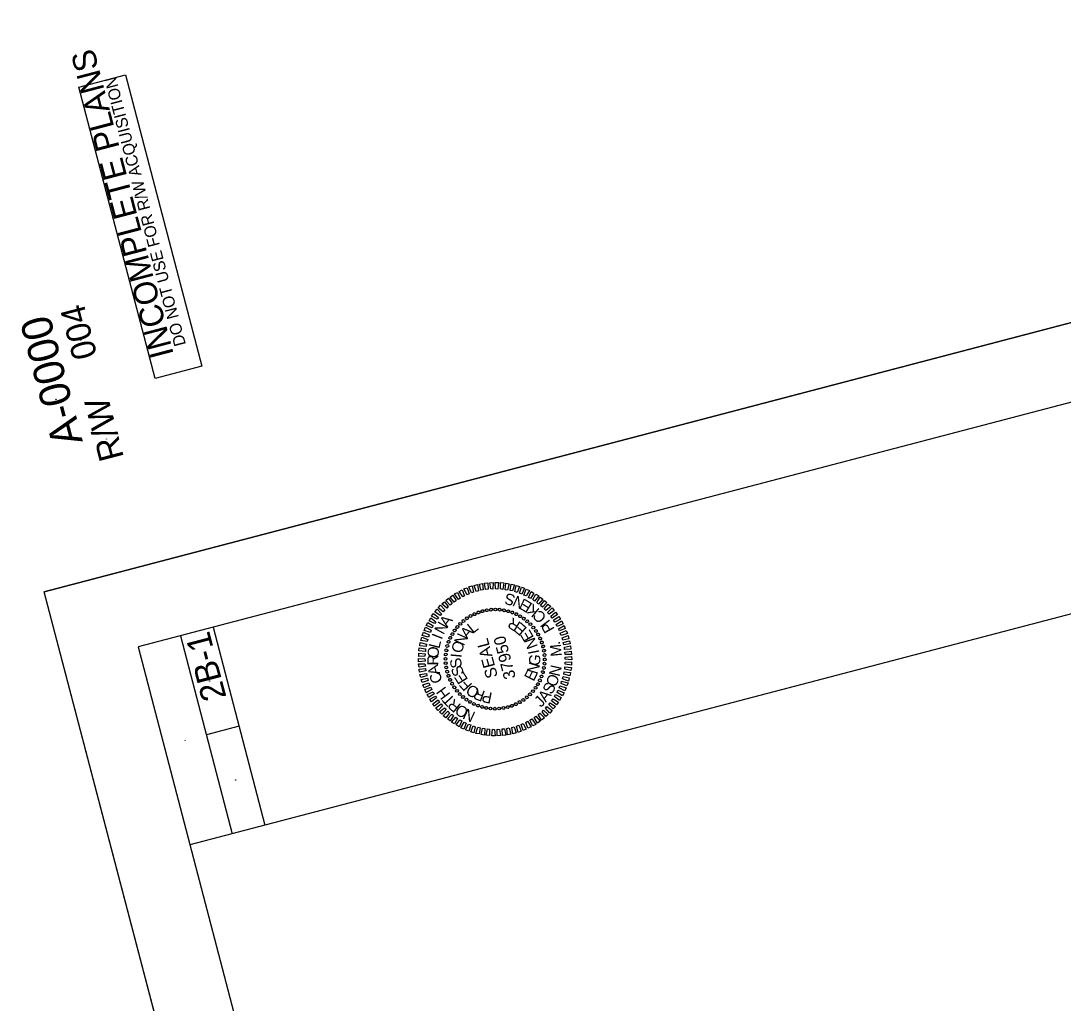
# Model space of a CAD drawing. Extents: x 1366699 to 1368206, y 878140 to 880064.
# Drawn here: x 1366699 to 1367209, y 879584 to 880064 of the extents above; entities that cross this region are included whole.
import ezdxf

# ---------------------------------------------------------------- set-up
doc = ezdxf.new("R2010")
doc.units = 0
for name, color, linetype in [('Prop Pavement Schedule Description CELL', 7, 'Continuous'), ('Prop Shade Medium', 7, 'Continuous'), ('Sheet_Title_Block_Text', 7, 'Continuous'), ('Typical ID Circle CELL', 7, 'Continuous'), ('Typical Terminator CELL', 7, 'Continuous'), ('Typical Text Label CELL', 7, 'Continuous')]:
    doc.layers.add(name, color=color, linetype=linetype)

msp = doc.modelspace()

# ---------------------------------------------------------------- linework, layer by layer
at = {"layer": 'Prop Pavement Schedule Description CELL'}
for centre in [(1366728.56, 879907.99), (1366716.56, 879879), (1366741.23, 879859.63)]:
    msp.add_circle(centre, 0.06, dxfattribs=at)
at = {"layer": 'Prop Shade Medium'}
for p, q in [((1367748.14, 880017.97), (1366756.62, 879758.15)), ((1367773.49, 879921.24), (1366781.97, 879661.42)), ((1366793.3, 879767.77), (1366818.65, 879671.03)), ((1366777.34, 879763.58), (1366802.69, 879666.85)), ((1366756.62, 879758.15), (1367168.57, 878186.24)), ((1366805.98, 879719.4), (1366790.02, 879715.22))]:
    msp.add_line(p, q, dxfattribs=at)
at = {"layer": 'Sheet_Title_Block_Text'}
for p in [(1367774.9, 880063.78), (1367141.8, 878140.46)]:
    msp.add_line(p, (1366710.84, 879784.92), dxfattribs=at)
for centre in [(1366791.66, 879741.49), (1366779.66, 879712.5), (1366804.33, 879693.13)]:
    msp.add_circle(centre, 0.06, dxfattribs=at)
at = {"layer": 'Typical ID Circle CELL'}
for p, q in [((1366922.91, 879774.97), (1366922.91, 879774.97)), ((1366924.95, 879775.59), (1366924.95, 879775.59)), ((1366927.03, 879776.03), (1366927.03, 879776.03)), ((1366929.12, 879776.27), (1366929.12, 879776.27)), ((1366931.19, 879776.39), (1366931.19, 879776.39)), ((1366933.33, 879776.29), (1366933.33, 879776.29)), ((1366935.42, 879775.98), (1366935.42, 879775.98)), ((1366937.5, 879775.56), (1366937.5, 879775.56)), ((1366939.5, 879774.86), (1366939.5, 879774.86)), ((1366915.61, 879770.81), (1366915.61, 879770.81)), ((1366917.26, 879772.08), (1366917.26, 879772.08)), ((1366919.05, 879773.19), (1366919.05, 879773.19)), ((1366920.99, 879774.13), (1366920.99, 879774.13)), ((1366941.48, 879774.07), (1366941.48, 879774.07)), ((1366943.31, 879773.08), (1366943.31, 879773.08)), ((1366945.14, 879771.93), (1366945.14, 879771.93)), ((1366946.75, 879770.63), (1366946.75, 879770.63)), ((1366911.29, 879766.19), (1366911.29, 879766.19)), ((1366912.59, 879767.81), (1366912.59, 879767.81)), ((1366914.06, 879769.38), (1366914.06, 879769.38)), ((1366948.32, 879769.17), (1366948.32, 879769.17)), ((1366949.76, 879767.61), (1366949.76, 879767.61)), ((1366951.03, 879765.97), (1366951.03, 879765.97)), ((1366908.36, 879760.55), (1366908.36, 879760.55)), ((1366909.16, 879762.53), (1366909.16, 879762.53)), ((1366910.14, 879764.37), (1366910.14, 879764.37)), ((1366952.13, 879764.17), (1366952.13, 879764.17)), ((1366953.08, 879762.23), (1366953.08, 879762.23)), ((1366953.92, 879760.31), (1366953.92, 879760.31)), ((1366907.24, 879756.48), (1366907.24, 879756.48)), ((1366907.67, 879758.55), (1366907.67, 879758.55)), ((1366954.54, 879758.28), (1366954.54, 879758.28)), ((1366954.97, 879756.19), (1366954.97, 879756.19)), ((1366906.83, 879752.25), (1366906.83, 879752.25)), ((1366906.93, 879754.39), (1366906.93, 879754.39)), ((1366906.96, 879750.18), (1366906.96, 879750.18)), ((1366931.08, 879752.14), (1366931.08, 879752.14)), ((1366955.21, 879754.1), (1366955.21, 879754.1)), ((1366955.24, 879749.89), (1366955.24, 879749.89)), ((1366955.34, 879752.03), (1366955.34, 879752.03)), ((1366907.19, 879748.09), (1366907.19, 879748.09)), ((1366907.63, 879746), (1366907.63, 879746)), ((1366954.5, 879745.73), (1366954.5, 879745.73)), ((1366954.92, 879747.8), (1366954.92, 879747.8)), ((1366908.25, 879743.97), (1366908.25, 879743.97)), ((1366909.09, 879742.05), (1366909.09, 879742.05)), ((1366910.03, 879740.11), (1366910.03, 879740.11)), ((1366952.02, 879739.91), (1366952.02, 879739.91)), ((1366953.01, 879741.75), (1366953.01, 879741.75)), ((1366953.81, 879743.73), (1366953.81, 879743.73)), ((1366911.14, 879738.31), (1366911.14, 879738.31)), ((1366912.41, 879736.66), (1366912.41, 879736.66)), ((1366913.85, 879735.11), (1366913.85, 879735.11)), ((1366948.11, 879734.9), (1366948.11, 879734.9)), ((1366949.58, 879736.47), (1366949.58, 879736.47)), ((1366950.88, 879738.09), (1366950.88, 879738.09)), ((1366915.41, 879733.64), (1366915.41, 879733.64)), ((1366917.03, 879732.34), (1366917.03, 879732.34)), ((1366918.86, 879731.2), (1366918.86, 879731.2)), ((1366920.69, 879730.21), (1366920.69, 879730.21)), ((1366922.67, 879729.41), (1366922.67, 879729.41)), ((1366939.25, 879729.31), (1366939.25, 879729.31)), ((1366941.17, 879730.14), (1366941.17, 879730.14)), ((1366943.11, 879731.09), (1366943.11, 879731.09)), ((1366944.91, 879732.2), (1366944.91, 879732.2)), ((1366946.56, 879733.46), (1366946.56, 879733.46)), ((1366924.67, 879728.72), (1366924.67, 879728.72)), ((1366926.74, 879728.3), (1366926.74, 879728.3)), ((1366928.84, 879727.99), (1366928.84, 879727.99)), ((1366930.97, 879727.88), (1366930.97, 879727.88)), ((1366933.04, 879728.01), (1366933.04, 879728.01)), ((1366935.13, 879728.25), (1366935.13, 879728.25)), ((1366937.22, 879728.69), (1366937.22, 879728.69))]:
    msp.add_line(p, q, dxfattribs=at)
for points in [[(1366915.23, 879782.5), (1366913.53, 879785.18), (1366915.03, 879785.9), (1366916.13, 879783.05)], [(1366917.35, 879783.54), (1366915.85, 879786.38), (1366917.39, 879786.97), (1366918.41, 879784.04)], [(1366919.5, 879784.45), (1366918.28, 879787.37), (1366919.84, 879787.9), (1366920.59, 879784.86)], [(1366921.81, 879785.14), (1366920.83, 879788.13), (1366922.41, 879788.57), (1366922.93, 879785.46)], [(1366924.15, 879785.75), (1366923.4, 879788.8), (1366924.96, 879789.14), (1366925.29, 879785.97)], [(1366926.45, 879786.15), (1366925.89, 879789.2), (1366927.52, 879789.46), (1366927.63, 879786.23)], [(1366928.93, 879786.44), (1366928.49, 879789.43), (1366930.16, 879789.55), (1366930.01, 879786.34)], [(1366931.32, 879786.46), (1366931.12, 879789.51), (1366932.74, 879789.62), (1366932.4, 879786.37)], [(1366933.75, 879786.39), (1366933.78, 879789.51), (1366935.39, 879789.31), (1366934.87, 879786.15)], [(1366936.06, 879786.04), (1366936.32, 879789.22), (1366937.95, 879788.93), (1366937.21, 879785.86)], [(1366938.46, 879785.71), (1366938.88, 879788.68), (1366940.52, 879788.39), (1366939.5, 879785.4)], [(1366940.77, 879785.15), (1366941.43, 879788.15), (1366943, 879787.58), (1366941.82, 879784.65)], [(1366943.02, 879784.28), (1366943.9, 879787.23), (1366945.49, 879786.73), (1366944.08, 879783.92)], [(1366945.18, 879783.38), (1366946.31, 879786.31), (1366947.81, 879785.63), (1366946.2, 879782.97)], [(1366947.4, 879782.25), (1366948.65, 879785.16), (1366950.04, 879784.29), (1366948.36, 879781.72)], [(1366907.45, 879777), (1366905.09, 879779.15), (1366906.36, 879780.16), (1366908.18, 879777.81)], [(1366909.19, 879778.49), (1366907.02, 879780.84), (1366908.34, 879781.87), (1366910.08, 879779.24)], [(1366911.14, 879779.94), (1366909.13, 879782.44), (1366910.43, 879783.36), (1366911.98, 879780.68)], [(1366913.16, 879781.31), (1366911.25, 879783.99), (1366912.71, 879784.7), (1366914.05, 879781.91)], [(1366949.46, 879781.18), (1366950.93, 879783.79), (1366952.36, 879782.99), (1366950.36, 879780.47)], [(1366951.43, 879779.72), (1366953.1, 879782.34), (1366954.42, 879781.36), (1366952.28, 879779.01)], [(1366953.32, 879778.34), (1366955.2, 879780.73), (1366956.43, 879779.77), (1366954.16, 879777.48)], [(1366904.18, 879773.47), (1366901.59, 879775.2), (1366902.69, 879776.47), (1366904.9, 879774.28)], [(1366905.74, 879775.22), (1366903.29, 879777.19), (1366904.43, 879778.46), (1366906.49, 879776.13)], [(1366955.05, 879776.62), (1366957.08, 879779.05), (1366958.23, 879777.82), (1366955.86, 879775.9)], [(1366956.73, 879774.94), (1366958.92, 879777.16), (1366959.97, 879775.9), (1366957.44, 879774.03)], [(1366958.28, 879773.17), (1366960.64, 879775.14), (1366961.59, 879773.9), (1366958.89, 879772.08)], [(1366900.38, 879767.34), (1366897.43, 879768.57), (1366898.23, 879770), (1366900.83, 879768.42)], [(1366901.54, 879769.47), (1366898.79, 879770.86), (1366899.6, 879772.29), (1366902.09, 879770.38)], [(1366902.76, 879771.57), (1366900.06, 879773.12), (1366901.04, 879774.45), (1366903.5, 879772.48)], [(1366959.66, 879771.1), (1366962.15, 879772.95), (1366962.98, 879771.63), (1366960.26, 879770.21)], [(1366960.89, 879769.04), (1366963.55, 879770.84), (1366964.32, 879769.34), (1366961.4, 879768.13)], [(1366898.58, 879762.87), (1366895.42, 879763.74), (1366896.06, 879765.23), (1366898.85, 879764.05)], [(1366899.44, 879765.17), (1366896.4, 879766.17), (1366897.08, 879767.67), (1366899.84, 879766.24)], [(1366962.03, 879766.95), (1366964.8, 879768.53), (1366965.37, 879767.03), (1366962.49, 879765.87)], [(1366962.94, 879764.79), (1366965.77, 879766.14), (1366966.4, 879764.62), (1366963.39, 879763.72)], [(1366897.36, 879758.27), (1366894.29, 879758.66), (1366894.54, 879760.28), (1366897.59, 879759.44)], [(1366897.83, 879760.71), (1366894.83, 879761.22), (1366895.23, 879762.83), (1366898.14, 879761.75)], [(1366963.82, 879762.54), (1366966.78, 879763.62), (1366967.16, 879762.07), (1366964.09, 879761.41)], [(1366964.41, 879760.29), (1366967.43, 879761.14), (1366967.81, 879759.59), (1366964.67, 879759.16)], [(1366896.82, 879753.6), (1366893.74, 879753.49), (1366893.8, 879755.06), (1366896.87, 879754.67)], [(1366897.07, 879755.93), (1366893.84, 879756.18), (1366894.03, 879757.64), (1366897.09, 879757.09)], [(1366964.92, 879757.93), (1366967.99, 879758.59), (1366968.14, 879756.98), (1366965.04, 879756.76)], [(1366965.17, 879755.59), (1366968.26, 879756.01), (1366968.46, 879754.41), (1366965.35, 879754.44)], [(1366896.84, 879751.2), (1366893.69, 879750.82), (1366893.62, 879752.5), (1366896.8, 879752.24)], [(1366896.99, 879748.69), (1366893.9, 879748.27), (1366893.7, 879749.87), (1366896.82, 879749.84)], [(1366965.35, 879750.68), (1366968.43, 879750.79), (1366968.37, 879749.22), (1366965.3, 879749.61)], [(1366965.33, 879753.08), (1366968.48, 879753.46), (1366968.55, 879751.78), (1366965.37, 879752.04)], [(1366897.25, 879746.35), (1366894.17, 879745.69), (1366894.02, 879747.3), (1366897.12, 879747.52)], [(1366897.76, 879743.99), (1366894.74, 879743.14), (1366894.36, 879744.68), (1366897.5, 879745.12)], [(1366964.8, 879746.01), (1366967.87, 879745.62), (1366967.63, 879743.99), (1366964.58, 879744.84)], [(1366965.1, 879748.35), (1366968.33, 879748.1), (1366968.14, 879746.65), (1366965.08, 879747.19)], [(1366898.34, 879741.74), (1366895.39, 879740.66), (1366895, 879742.21), (1366898.08, 879742.87)], [(1366899.23, 879739.48), (1366896.39, 879738.13), (1366895.77, 879739.66), (1366898.77, 879740.56)], [(1366963.59, 879741.41), (1366966.74, 879740.53), (1366966.1, 879739.05), (1366963.32, 879740.23)], [(1366964.33, 879743.57), (1366967.34, 879743.06), (1366966.94, 879741.45), (1366964.03, 879742.53)], [(1366900.13, 879737.33), (1366897.37, 879735.75), (1366896.8, 879737.24), (1366899.68, 879738.41)], [(1366901.27, 879735.24), (1366898.62, 879733.44), (1366897.85, 879734.93), (1366900.76, 879736.15)], [(1366902.5, 879733.18), (1366900.01, 879731.33), (1366899.19, 879732.65), (1366901.9, 879734.06)], [(1366960.63, 879734.8), (1366963.37, 879733.42), (1366962.57, 879731.99), (1366960.08, 879733.9)], [(1366961.79, 879736.93), (1366964.74, 879735.71), (1366963.93, 879734.28), (1366961.33, 879735.86)], [(1366962.73, 879739.11), (1366965.77, 879738.11), (1366965.09, 879736.61), (1366962.33, 879738.04)], [(1366903.89, 879731.11), (1366901.53, 879729.14), (1366900.58, 879730.38), (1366903.28, 879732.19)], [(1366905.44, 879729.34), (1366903.25, 879727.12), (1366902.2, 879728.38), (1366904.73, 879730.24)], [(1366956.42, 879729.06), (1366958.88, 879727.09), (1366957.74, 879725.82), (1366955.68, 879728.15)], [(1366957.99, 879730.81), (1366960.58, 879729.07), (1366959.48, 879727.81), (1366957.26, 879730)], [(1366959.41, 879732.71), (1366962.1, 879731.16), (1366961.12, 879729.83), (1366958.66, 879731.8)], [(1366907.11, 879727.65), (1366905.09, 879725.23), (1366903.94, 879726.46), (1366906.31, 879728.38)], [(1366908.85, 879725.93), (1366906.96, 879723.55), (1366905.74, 879724.51), (1366908.01, 879726.8)], [(1366910.74, 879724.56), (1366909.07, 879721.93), (1366907.74, 879722.92), (1366909.89, 879725.27)], [(1366951.03, 879724.34), (1366953.03, 879721.84), (1366951.74, 879720.93), (1366950.18, 879723.6)], [(1366952.98, 879725.79), (1366955.14, 879723.44), (1366953.82, 879722.41), (1366952.09, 879725.03)], [(1366954.72, 879727.28), (1366957.07, 879725.13), (1366955.8, 879724.13), (1366953.99, 879726.47)], [(1366912.7, 879723.1), (1366911.23, 879720.48), (1366909.8, 879721.29), (1366911.81, 879723.81)], [(1366914.76, 879722.03), (1366913.52, 879719.12), (1366912.13, 879719.98), (1366913.81, 879722.56)], [(1366916.98, 879720.9), (1366915.85, 879717.97), (1366914.36, 879718.65), (1366915.97, 879721.31)], [(1366919.14, 879720), (1366918.27, 879717.04), (1366916.67, 879717.55), (1366918.09, 879720.36)], [(1366921.39, 879719.13), (1366920.73, 879716.13), (1366919.17, 879716.69), (1366920.35, 879719.63)], [(1366923.71, 879718.57), (1366923.29, 879715.59), (1366921.65, 879715.89), (1366922.67, 879718.88)], [(1366940.35, 879719.13), (1366941.34, 879716.15), (1366939.76, 879715.71), (1366939.24, 879718.82)], [(1366942.66, 879719.83), (1366943.88, 879716.91), (1366942.33, 879716.38), (1366941.57, 879719.42)], [(1366944.82, 879720.74), (1366946.31, 879717.9), (1366944.78, 879717.31), (1366943.75, 879720.24)], [(1366946.93, 879721.78), (1366948.64, 879719.1), (1366947.13, 879718.38), (1366946.03, 879721.23)], [(1366949.01, 879722.97), (1366950.91, 879720.29), (1366949.45, 879719.58), (1366948.12, 879722.37)], [(1366926.11, 879718.24), (1366925.85, 879715.06), (1366924.21, 879715.35), (1366924.95, 879718.42)], [(1366928.41, 879717.89), (1366928.39, 879714.77), (1366926.77, 879714.97), (1366927.29, 879718.12)], [(1366930.84, 879717.81), (1366931.05, 879714.76), (1366929.42, 879714.66), (1366929.76, 879717.91)], [(1366933.24, 879717.84), (1366933.68, 879714.85), (1366932.01, 879714.73), (1366932.16, 879717.94)], [(1366935.72, 879718.13), (1366936.27, 879715.08), (1366934.64, 879714.82), (1366934.54, 879718.05)], [(1366938.01, 879718.53), (1366938.77, 879715.48), (1366937.21, 879715.14), (1366936.87, 879718.3)]]:
    msp.add_lwpolyline(points, close=True, dxfattribs=at)
for centre, major_axis, ratio in [((1366920.97, 879774.14), (-0.289, 0.632), 0.999706), ((1366922.92, 879774.94), (-0.234, 0.655), 0.999706), ((1366924.94, 879775.57), (-0.176, 0.673), 0.999706), ((1366927.01, 879776.01), (-0.117, 0.685), 0.999706), ((1366929.1, 879776.28), (-0.058, 0.693), 0.999706), ((1366931.22, 879776.36), (0.002, 0.695), 0.999706), ((1366933.33, 879776.25), (0.063, 0.693), 0.999706), ((1366935.42, 879775.97), (0.122, 0.684), 0.999707), ((1366937.48, 879775.5), (0.181, 0.671), 0.999707), ((1366939.49, 879774.85), (0.239, 0.653), 0.999707), ((1366941.44, 879774.03), (0.295, 0.63), 0.999708), ((1366914.05, 879769.36), (-0.487, 0.496), 0.999707), ((1366915.62, 879770.78), (-0.442, 0.537), 0.999707), ((1366917.3, 879772.05), (-0.394, 0.573), 0.999706), ((1366919.09, 879773.18), (-0.343, 0.605), 0.999706), ((1366943.31, 879773.05), (0.348, 0.602), 0.999708), ((1366945.08, 879771.9), (0.4, 0.569), 0.999709), ((1366946.75, 879770.61), (0.448, 0.532), 0.999709), ((1366948.3, 879769.17), (0.493, 0.491), 0.99971), ((1366910.17, 879764.36), (-0.599, 0.353), 0.999708), ((1366911.32, 879766.14), (-0.566, 0.404), 0.999708), ((1366912.61, 879767.81), (-0.528, 0.452), 0.999707), ((1366949.72, 879767.6), (0.534, 0.446), 0.99971), ((1366951, 879765.92), (0.571, 0.397), 0.99971), ((1366952.13, 879764.13), (0.603, 0.346), 0.99971), ((1366908.37, 879760.55), (-0.651, 0.244), 0.999709), ((1366909.19, 879762.49), (-0.627, 0.3), 0.999709), ((1366953.09, 879762.25), (0.631, 0.291), 0.999711), ((1366953.89, 879760.3), (0.655, 0.235), 0.999711), ((1366906.97, 879754.38), (-0.692, 0.066), 0.99971), ((1366907.25, 879756.47), (-0.684, 0.127), 0.99971), ((1366907.72, 879758.53), (-0.67, 0.186), 0.99971), ((1366954.51, 879758.28), (0.673, 0.176), 0.999711), ((1366954.96, 879756.21), (0.686, 0.116), 0.999711), ((1366955.22, 879754.11), (0.693, 0.056), 0.999711), ((1366906.86, 879752.27), (-0.695, 0.005), 0.99971), ((1366906.94, 879750.16), (-0.693, -0.056), 0.999711), ((1366955.2, 879749.89), (0.692, -0.066), 0.99971), ((1366955.3, 879752), (0.695, -0.005), 0.99971), ((1366907.21, 879748.06), (-0.686, -0.116), 0.999711), ((1366907.65, 879746), (-0.673, -0.176), 0.999711), ((1366908.28, 879743.98), (-0.655, -0.235), 0.999711), ((1366953.8, 879743.73), (0.651, -0.244), 0.999709), ((1366954.44, 879745.74), (0.67, -0.186), 0.99971), ((1366954.91, 879747.8), (0.684, -0.127), 0.99971), ((1366909.08, 879742.02), (-0.631, -0.291), 0.999711), ((1366910.04, 879740.14), (-0.603, -0.346), 0.99971), ((1366951.99, 879739.91), (0.599, -0.353), 0.999708), ((1366952.98, 879741.78), (0.627, -0.3), 0.999709), ((1366911.17, 879738.35), (-0.571, -0.397), 0.99971), ((1366912.44, 879736.67), (-0.534, -0.446), 0.99971), ((1366913.86, 879735.1), (-0.493, -0.491), 0.99971), ((1366915.41, 879733.67), (-0.448, -0.532), 0.999709), ((1366946.55, 879733.5), (0.442, -0.537), 0.999707), ((1366948.12, 879734.92), (0.487, -0.496), 0.999707), ((1366949.55, 879736.47), (0.528, -0.452), 0.999707), ((1366950.85, 879738.14), (0.566, -0.404), 0.999708), ((1366917.08, 879732.37), (-0.4, -0.569), 0.999709), ((1366918.86, 879731.23), (-0.348, -0.602), 0.999708), ((1366920.73, 879730.24), (-0.295, -0.63), 0.999708), ((1366922.67, 879729.42), (-0.239, -0.653), 0.999707), ((1366924.69, 879728.78), (-0.181, -0.671), 0.999707), ((1366926.75, 879728.31), (-0.122, -0.684), 0.999707), ((1366935.16, 879728.26), (0.117, -0.685), 0.999706), ((1366937.22, 879728.71), (0.176, -0.673), 0.999706), ((1366939.24, 879729.33), (0.234, -0.655), 0.999706), ((1366941.2, 879730.13), (0.289, -0.632), 0.999706), ((1366943.08, 879731.09), (0.343, -0.605), 0.999706), ((1366944.87, 879732.22), (0.394, -0.573), 0.999706), ((1366928.84, 879728.02), (-0.063, -0.693), 0.999706), ((1366930.95, 879727.92), (-0.002, -0.695), 0.999706), ((1366933.06, 879728), (0.058, -0.693), 0.999706)]:
    msp.add_ellipse(centre, major_axis=major_axis, ratio=ratio, dxfattribs=at)
at = {"layer": 'Typical Terminator CELL'}
msp.add_lwpolyline([(1367141.8, 878140.46), (1366710.84, 879784.92), (1367774.9, 880063.78), (1368205.86, 878419.32)], close=True, dxfattribs=at)
at = {"layer": 'Typical Text Label CELL'}
msp.add_lwpolyline([(1366787.76, 879895.18), (1366765.02, 879889.22), (1366727.76, 880031.42), (1366750.49, 880037.38)], close=True, dxfattribs=at)

# ---------------------------------------------------------------- texts
at = {"layer": 'Prop Pavement Schedule Description CELL'}
for s, height, p in [('004', 12, (1366736.79, 879900.27)), ('A-0000', 15, (1366729.71, 879858.4)), ('R/W', 12, (1366749.79, 879850.65)), ('2B-1', 12.003, (1366799.88, 879733.54))]:
    msp.add_text(s, height=height, rotation=104.6851, dxfattribs=at).set_placement(p)
at = {"layer": 'Typical ID Circle CELL'}
for s, height, rotation, p in [('S', 5.46, 164.7452, (1366941.34, 879783.23)), ('N', 5.46, 155.468, (1366946.21, 879781.17)), ('E', 5.46, 148.3514, (1366949.69, 879779.07)), ('K', 5.46, 140.5331, (1366953.18, 879776.29)), ('C', 5.46, 131.9391, (1366956.54, 879772.71)), ('N', 5.45, 61.5041, (1366905.85, 879763.76)), ('A', 5.45, 54.3023, (1366907.83, 879767.27)), ('R', 5.45, 148.1665, (1366943.91, 879769.88)), ('E', 5.45, 138.8091, (1366947.02, 879767.19)), ('I', 5.46, 126.7985, (1366958.28, 879770.35)), ('N', 5.45, 66.1618, (1366915.8, 879758.32)), ('A', 5.45, 47.4454, (1366917.48, 879761.65)), ('L', 5.45, 38.086, (1366920.18, 879764.37)), ('E', 5.45, 120.0968, (1366950.22, 879762.77)), ('P', 5.46, 119.6819, (1366960.33, 879766.84)), ('L', 5.45, 75.906, (1366903.8, 879756.96)), ('I', 5.45, 68.7053, (1366904.97, 879761.35)), ('O', 5.45, 75.5187, (1366914.82, 879754.69)), ('SEAL', 5.793, 104.8532, (1366932.46, 879743.65)), ('37950', 5.794, 104.6851, (1366941.25, 879743.14)), ('N', 5.44, 110.7415, (1366952.07, 879758.32)), ('.', 5.46, 105.4395, (1366963.05, 879759.19)), ('O', 5.44, 83.1063, (1366903.23, 879752.38)), ('I', 5.45, 84.8748, (1366914.69, 879752.64)), ('I', 5.44, 101.3863, (1366952.8, 879755.17)), ('M', 5.46, 95.6821, (1366963.78, 879753.67)), ('R', 5.45, 90.3062, (1366903.41, 879749.07)), ('A', 5.44, 104.7054, (1366904.32, 879745.12)), ('S', 5.44, 103.5855, (1366915.16, 879748.46)), ('N', 5.45, 73.3191, (1366951.65, 879744.47)), ('G', 5.45, 82.6754, (1366952.75, 879748.59)), ('C', 5.44, 111.905, (1366905.62, 879741.52)), ('S', 5.44, 112.9407, (1366916.15, 879745.13)), ('E', 5.45, 122.2961, (1366918.03, 879742.19)), ('E', 5.45, 63.9621, (1366949.92, 879740.97)), ('O', 5.46, 67.6659, (1366960.67, 879738.13)), ('N', 5.46, 77.4417, (1366962.61, 879743.36)), ('F', 5.44, 131.6521, (1366920.26, 879739.61)), ('O', 5.45, 150.3663, (1366923.86, 879737.31)), ('S', 5.46, 60.42, (1366958.66, 879734.51)), ('H', 5.45, 126.3045, (1366909.47, 879734.98)), ('T', 5.45, 133.5048, (1366911.85, 879732.39)), ('R', 5.45, 159.7247, (1366926.6, 879736.33)), ('P', 5.45, 169.0839, (1366929.99, 879735.67)), ('J', 5.46, 46.2588, (1366953.51, 879728.3)), ('A', 5.46, 52.2692, (1366955.88, 879730.78)), ('R', 5.45, 140.7056, (1366914.79, 879729.8)), ('O', 5.45, 147.9068, (1366918.57, 879727.4)), ('N', 5.45, 155.1085, (1366921.87, 879726.02))]:
    msp.add_text(s, height=height, rotation=rotation, dxfattribs=at).set_placement(p)
at = {"layer": 'Typical Text Label CELL'}
for s, height, p in [('INCOMPLETE PLANS', 11.52, (1366774.17, 879900.87)), ('DO NOT USE FOR R/W ACQUISITION', 5.76, (1366780.07, 879905.78))]:
    msp.add_text(s, height=height, rotation=104.6851, dxfattribs=at).set_placement(p)

doc.saveas('drawing.dxf')
